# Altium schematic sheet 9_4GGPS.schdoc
size 309 x 223 mm; Symbol: Sheet-Symbol_A4; Device: Sheet-Symbol_A4; Company: 嘉立创EDA; Version: V1.0; Page Size: A4; @Project Name: 共享电动车中控; @Page Count: 11; @Update Date: 2024-11-20; @Create Date: 2024-09-23; @Schematic Name: SCH; @Page No: 9; @Page Name: 4GGPS; @Board Name: STM32F103C8T6; @Create Time: 08:32:53; @Update Time: 04:51:40
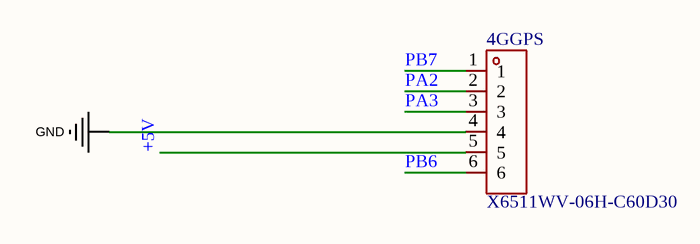
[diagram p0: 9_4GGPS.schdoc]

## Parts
4GGPS  X6511WV-06H-C60D30  [HDR-TH_6P-P2.54-V-M]  (value not drawn)

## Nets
GND: 4GGPS.4
+5V: 4GGPS.5
PA2: 4GGPS.2
PA3: 4GGPS.3
PB6: 4GGPS.6
PB7: 4GGPS.1

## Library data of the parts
4GGPS = X6511WV-06H-C60D30: 插针结构:1x6P;间距:2.54mm;行距:2.54mm;圆针/方针:方针;安装类型:-;排数:单排;总PIN位数:6P;额定电流:3A;额定电压:250V;配合针长度:-;塑高:2.5mm;端接针长度:-;触头材质:黄铜;触头镀层:金;工作温度范围:-40℃~+105℃;焊接温度(最大值):260℃;颜色:黑色;; Manufacturer: XKB Connection(中国星坤); Symbol: X6511WV-06H-C30D60; Add into BOM: yes; Pin Structure: 1x6P; Pitch: 2.54mm; Circluar Pins/Square Pins: 方针; Current Rating (Max): 3A; Voltage Rating (Max): 250V; Soldering Temperature(Max): 260℃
